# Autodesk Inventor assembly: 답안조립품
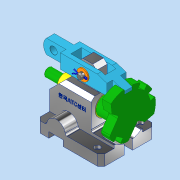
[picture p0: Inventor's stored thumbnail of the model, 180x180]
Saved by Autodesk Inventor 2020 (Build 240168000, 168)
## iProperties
Created: 2022-08
Part Number: 답안조립품
Document SubType Name: Assembly
Designer: user
Mass: 1243.79 g
Surface Area: 668.839 cm^2
Volume: 279.634 cm^3
Density: 4.44794 g/cm^3
Author: user
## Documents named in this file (8)
- C:\Users\user\Desktop\720806V1010\답안조립품.iam
- C:\Users\user\Desktop\720806V1010\본체.ipt
- C:\Users\user\Desktop\720806V1010\부시.ipt
- C:\Users\user\Desktop\720806V1010\분할대.ipt
- C:\Users\user\Desktop\720806V1010\분할축.ipt
- C:\Users\user\Desktop\720806V1010\분할핀.ipt
- C:\Users\user\Desktop\720806V1010\와셔.ipt
- C:\Users\user\Desktop\720806V1010\클레비스핀.ipt
